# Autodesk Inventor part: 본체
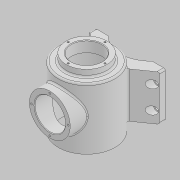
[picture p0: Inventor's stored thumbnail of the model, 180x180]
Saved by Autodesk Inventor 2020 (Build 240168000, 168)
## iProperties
Created: 2023-12
Part Number: 본체
Material: 일반
Document SubType Name: Modeling
Designer: 1강의실14
Density: 1 g/cm^3
Appearance: 기본값
Author: 1강의실14
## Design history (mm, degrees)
sketch "스케치1"
  geometry: L1 (-62, -77)-(-38.5, -77); L2 (-62, -77)-(-62, -67); L3 (-62, -67)-(-26.694, -42.278); L4 (38.5, -77)-(62, -77); L5 (62, -77)-(62, -67); L6 (62, -67)-(26.694, -42.278); A1 r 50 centre (0, 0) between (-26.694, -42.278) and (26.694, -42.278); A2 r 52.096 centre (0, -112.096) between (0, -60) and (-38.5, -77); A3 r 52.096 centre (0, -112.096) between (38.5, -77) and (0, -60); 1 further point
  constraints: 12 end point, 6 point on circle, 3 centre point, 1 coincident, 1 concentric, 1 horizontal, 1 perpendicular, 1 vertical, 1 vertical alignment
  dimensions: "d0" = 23.5 distance of L1.end L1.start; "d1" = 10 distance of L1.start L2.end; "d2" = 55 deg angle of L3 L2; "d5" = 100 diameter of A1; "d9" = 23.5 distance of L4.start L4.end; "d10" = 10 distance of L4.end L5.end; "d11" = 55 deg angle of L5 L6; "d16" = 38.5 horizontal distance of L4.start A2.start; "d17" = 17 distance from line of L1 A2.start; "d18" = 110 deg angle of L3 L6; "d19" = 62 distance from line of A3.centre L5; "d20" = 77 distance from line of L1 point (0, 0); "d21" = 52.09559 radius of A2; "d22" = 72.50188 distance from line of A3.centre L6
extrude "돌출2" new body sketch "스케치1" distance "d25" = 80; taper "d26" = 0 deg
feature "본체 이동1"
extrude "돌출3" join sketch "스케치1" distance "d30" = 108; taper "d31" = 0 deg
sketch "스케치2"
  geometry: C1 r 36 at (0, 0); 1 further point
  constraints: 1 centre point, 1 coincident
  dimensions: "d32" = 72 diameter of C1
extrude "돌출4" join sketch "스케치2" distance "d33" = 12; taper "d34" = 0 deg
sketch "스케치3"
  geometry: 2 further points
  constraints: 1 coincident
hole "구멍1" sketch "스케치3" at (0, 0) diameter "d35" = 54; stored, may be unused: countersink angle "d39" = 90 deg, drill point angle "d41" = 0 deg; dims "d36" = 8, "d37" = 54, "d38" = 4, "d40" = 19
sketch "스케치4"
  geometry: 2 further points
  constraints: 1 coincident
node "작업 평면2"
sketch "스케치7"
  geometry: C1 r 36 at (0, -50); 1 further point
  constraints: 1 centre point, 1 vertical alignment
  dimensions: "d43" = 72 diameter of C1; "d44" = 50 distance of C1.centre point (0, 0)
extrude "돌출5" join sketch "스케치7" stored distance "d45" = 12; taper "d46" = 0 deg
sketch "스케치9"
  geometry: C1 r 27 at (0, 0) reference; 5 further points
  constraints: 2 vertical alignment, 1 horizontal alignment
  dimensions: "d54" = 65 distance of point (32.5, 0) point (-32.5, 0); "d55" = 65 distance of point (0, 32.5) point (0, -32.5); "d56" = 32.5 distance of C1.centre point (0, 32.5); "d57" = 32.5 distance of point (32.5, 0) C1.centre; "d58" = 32.5 distance of point (-32.5, 0) C1.centre
node "작업 평면3"
sketch "스케치13"
  geometry: L1 (-38.5, -20)-(-62, -20) reference; L2 (62, -20)-(38.5, -20) reference; L3 (38.5, -100)-(62, -100) reference; L4 (-62, -20)-(-62, -100) reference; 5 further points
  constraints: 1 vertical alignment
  dimensions: "d72" = 20 distance from line of point (-54, -40) L1; "d73" = 108 distance of point (54, -40) point (-54, -40); "d74" = 20 distance from line of point (54, -40) L2; "d75" = 40 distance of point (54, -80) point (54, -40); "d76" = 20 distance from line of L3 point (54, -80); "d77" = 40 distance of point (-54, -80) point (-54, -40); "d78" = 8 distance from line of L4 point (-54, -40)
hole "구멍3" sketch "스케치13" at (54, -40), (-54, -40), (-54, -80), (54, -80) diameter "d79" = 9; stored, may be unused: countersink angle "d83" = 90 deg, drill point angle "d85" = 0 deg; dims "d80" = 8, "d81" = 54, "d82" = 4, "d84" = 6
sketch "스케치14"
  geometry: C1 r 4.5 at (108, 0) reference; C2 r 4.5 at (108, -40) reference; C3 r 4.5 at (0, -40) reference; C4 r 4.5 at (108, 0) reference; C5 r 4.5 at (0, -40) reference; 5 further points
  constraints: 3 coincident
hole "구멍4" sketch "스케치14" diameter "d86" = 14; stored, may be unused: countersink angle "d90" = 90 deg, drill point angle "d92" = 0 deg; dims "d87" = 8, "d88" = 54, "d89" = 4, "d91" = 6
hole "구멍5" sketch "스케치14" diameter "d93" = 14; stored, may be unused: countersink angle "d97" = 90 deg, drill point angle "d99" = 0 deg; dims "d94" = 8, "d95" = 54, "d96" = 4, "d98" = 6
hole "구멍6" sketch "스케치14" diameter "d100" = 14; stored, may be unused: countersink angle "d104" = 90 deg, drill point angle "d106" = 0 deg; dims "d101" = 8, "d102" = 54, "d103" = 4, "d105" = 6
hole "구멍7" sketch "스케치14" diameter "d107" = 14; stored, may be unused: countersink angle "d111" = 90 deg, drill point angle "d113" = 0 deg; dims "d108" = 8, "d109" = 54, "d110" = 4, "d112" = 6
fillet "모깎기1" dims "d114" = 3
fillet "모깎기2" dims "d115" = 3
fillet "모깎기3" dims "d116" = 3
sketch "스케치15"
  geometry: 2 further points
hole "구멍8" sketch "스케치15" at (0, 0) diameter "d117" = 54; stored, may be unused: countersink angle "d121" = 90 deg, drill point angle "d123" = 0 deg; dims "d118" = 8, "d119" = 54, "d120" = 4, "d122" = 85
sketch "스케치16"
  geometry: C1 r 27 at (0, 0) reference; 4 further points
  constraints: 2 horizontal alignment, 2 vertical alignment
  dimensions: "d124" = 65 distance of point (-32.5, 0) point (32.5, 0); "d125" = 65 distance of point (0, 32.5) point (0, -32.5); "d126" = 32.5 distance of C1.centre point (32.5, 0); "d127" = 32.5 distance of C1.centre point (0, -32.5)
hole "구멍9" sketch "스케치16" at (32.5, 0), (0, 32.5), (-32.5, 0), (0, -32.5) diameter "d128" = 3.242; stored, may be unused: countersink angle "d132" = 90 deg, drill point angle "d134" = 118 deg; dims "d129" = 8, "d130" = 54, "d131" = 4, "d133" = 10
sketch "스케치17"
  geometry: C1 r 27 at (0, 0) reference; 5 further points
  constraints: 2 horizontal alignment, 2 vertical alignment
  dimensions: "d135" = 65 distance of point (-32.5, 0) point (32.5, 0); "d136" = 65 distance of point (0, 32.5) point (0, -32.5); "d137" = 32.5 distance of point (0, 0) point (32.5, 0); "d138" = 32.5 distance of point (0, 0) point (0, -32.5)
hole "구멍10" sketch "스케치17" at (32.5, 0), (0, 32.5), (-32.5, 0), (0, -32.5) diameter "d139" = 3.242; stored, may be unused: countersink angle "d143" = 90 deg, drill point angle "d145" = 118 deg; dims "d140" = 8, "d141" = 54, "d142" = 4, "d144" = 10
node "작업 평면4"
node "작업 평면5"
sketch "스케치20"
  geometry: 2 further points
  constraints: 1 other
  dimensions: "d147" = 50 horizontal distance of point (0, 0) point (-50, 0.457)
feature "엠보싱1" sketch "스케치20" dims "d148" = 0.5, "d149" = 0
hole "구멍11" sketch "스케치4" diameter "d150" = 86; stored, may be unused: countersink angle "d154" = 90 deg, drill point angle "d156" = 0 deg; dims "d151" = 8, "d152" = 54, "d153" = 2, "d155" = 10
fillet "모깎기4" dims "d157" = 3
fillet "모깎기5" dims "d158" = 3
chamfer "모따기1" distance "d159" = 1; stored, may be unused: second distance "d160" = 2, angle "d161" = 45 deg
chamfer "모따기2" distance "d162" = 1; stored, may be unused: second distance "d163" = 2, angle "d164" = 45 deg
node "솔리드2"
feature "A9D066F2-1C7D-4E18-AEED-F7BC21143FA4" dims "d35" = 54, "d36" = 8, "d37" = 54, "d38" = 4, "d39" = 90 deg, "d40" = 19, "d41" = 0
other parameters: "d27" = 0, "d29" = 0, "d42" = 65, "d71" = -77, "d146" = -55
